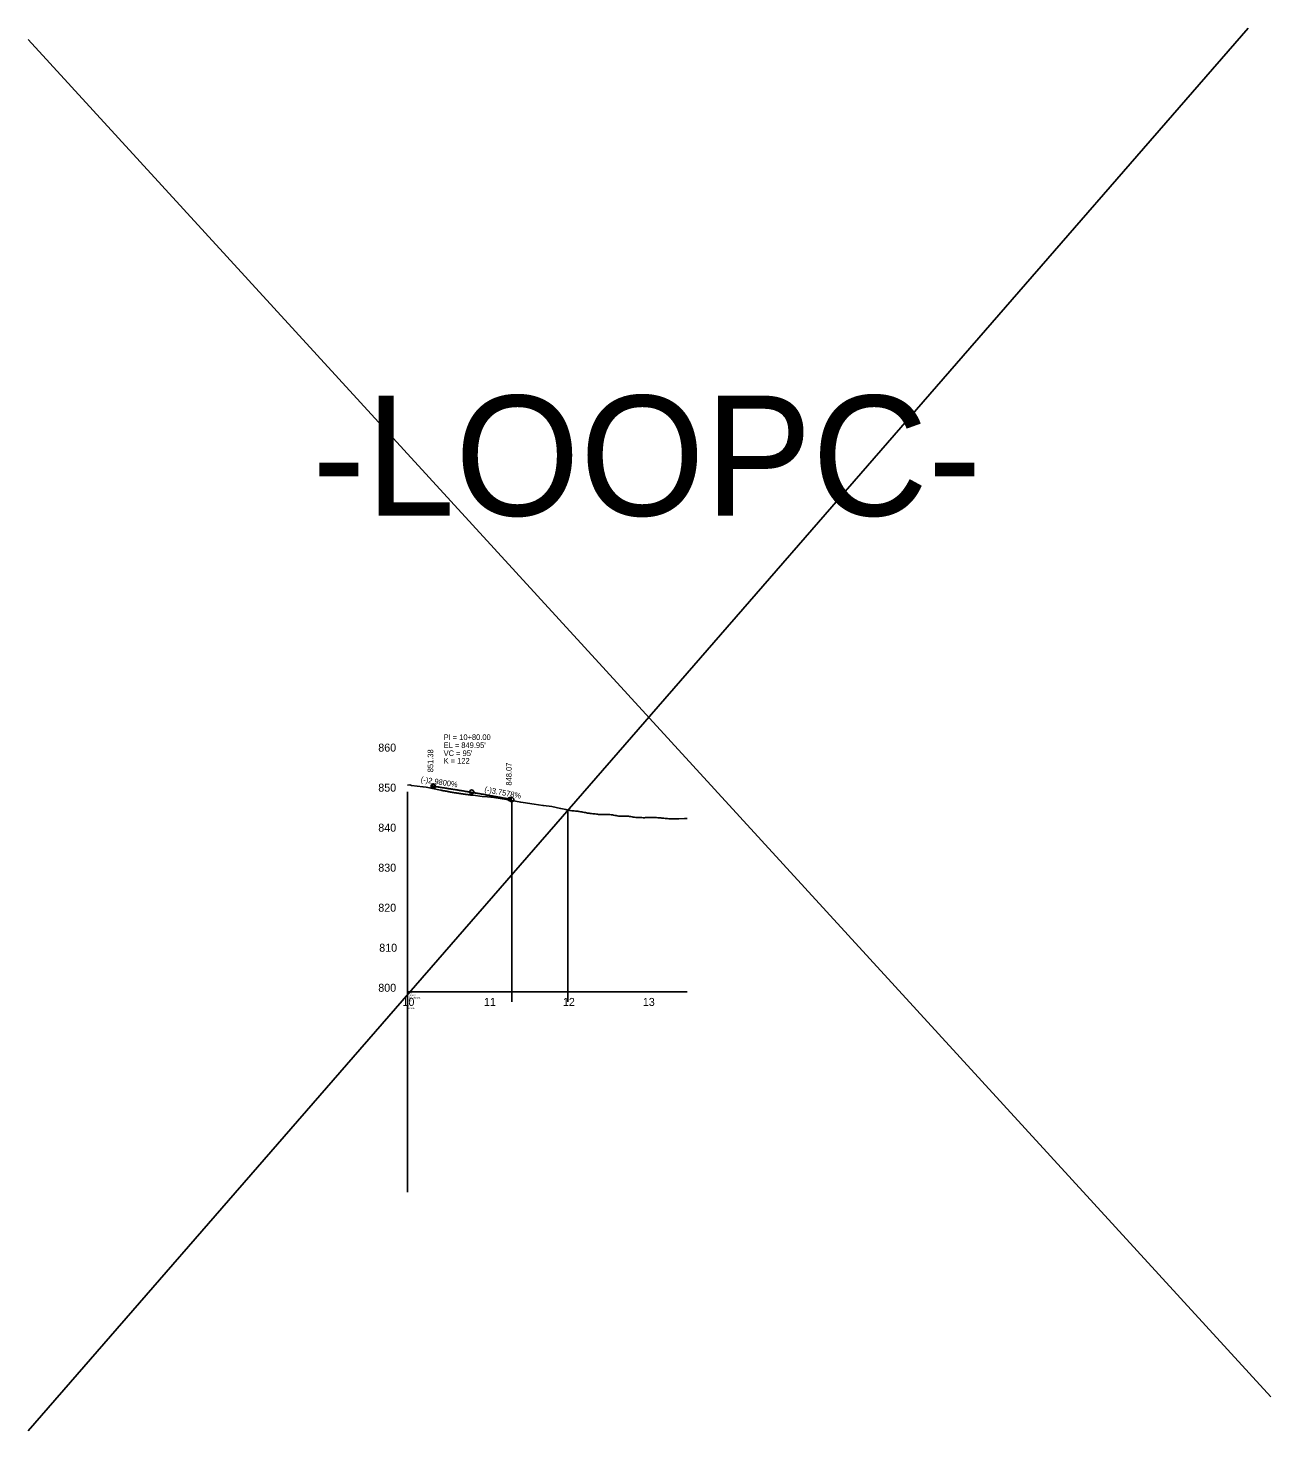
# Model space of a CAD drawing. Extents: x 570622 to 580296, y -55533 to -48575.
# Drawn here: x 578744 to 580296, y -52134 to -50382 of the extents above; entities that cross this region are included whole.
import ezdxf

# ---------------------------------------------------------------- set-up
doc = ezdxf.new("R2010")
doc.units = 0
for name, color, linetype in [('Default', 7, 'Continuous'), ('Exist Profile Cell', 7, 'Continuous'), ('Exist Vertical Profile Ground Line', 7, 'Continuous'), ('Exist Vertical Profile Horizontal Axis Label Major', 7, 'Continuous'), ('Exist Vertical Profile Vertical Axis Label', 7, 'Continuous'), ('Prop Vertical Profile Curve Label', 7, 'Continuous'), ('Prop Vertical Profile Grade', 7, 'Continuous'), ('Prop Vertical Profile Grade Label', 7, 'Continuous'), ('Prop VPI Label', 7, 'Continuous')]:
    doc.layers.add(name, color=color, linetype=linetype)

msp = doc.modelspace()

# ---------------------------------------------------------------- linework, layer by layer
at = {"layer": 'Default'}
for p, q in [((580267.7, -50381.9), (578744, -52134.4)), ((578744, -50396.2), (580296.2, -52091.7)), ((579348, -51598.5), (579348, -51346.9)), ((579418, -51598.5), (579418, -51359))]:
    msp.add_line(p, q, dxfattribs=at)
at = {"layer": 'Exist Profile Cell'}
for q in [(579218, -51336), (579567, -51586), (579218, -51836)]:
    msp.add_line((579218, -51586), q, dxfattribs=at)
at = {"layer": 'Exist Vertical Profile Ground Line'}
for points in [[(579218, -51327.6), (579220.8, -51327.5), (579220.8, -51327.5), (579223, -51328), (579237.2, -51329.6), (579241.2, -51330.4), (579259.3, -51334), (579260.1, -51334.1), (579260.8, -51334.3), (579261.6, -51334.4), (579262.4, -51334.6), (579263.1, -51334.7), (579263.9, -51334.8), (579264.7, -51335), (579265.5, -51335.1), (579266.2, -51335.3), (579267, -51335.4), (579267.8, -51335.6), (579268.5, -51335.7), (579269.3, -51335.9), (579270.1, -51336), (579270.9, -51336.1), (579271.6, -51336.3), (579272.4, -51336.4), (579273.2, -51336.5), (579273.2, -51336.6), (579273.9, -51336.7), (579274.7, -51336.8), (579275.5, -51337), (579275.6, -51337), (579276.3, -51337.1), (579277, -51337.2), (579277.8, -51337.3), (579278.6, -51337.4), (579279.3, -51337.5), (579280.1, -51337.7), (579280.4, -51337.7), (579280.9, -51337.8), (579281.7, -51337.9), (579282.4, -51338), (579283.2, -51338.1), (579284, -51338.2), (579284.7, -51338.4), (579285.5, -51338.5), (579286.3, -51338.6), (579287.1, -51338.7), (579287.8, -51338.8), (579288.6, -51338.9), (579289.4, -51339), (579290.1, -51339.1), (579290.9, -51339.2), (579291.7, -51339.3), (579292.5, -51339.4), (579293.2, -51339.5), (579294, -51339.6), (579294, -51339.6), (579294.8, -51339.7), (579295.5, -51339.8), (579296.3, -51339.9), (579297.1, -51340), (579297.9, -51340.1), (579300, -51340.3), (579311.2, -51341.7), (579317.6, -51342.4), (579325.8, -51343.3), (579341.5, -51345.8), (579346, -51346.5), (579359.3, -51349), (579362.4, -51349.4), (579376.1, -51351.4), (579386.9, -51353.2), (579387.6, -51353.3), (579398.3, -51354.5), (579408.9, -51356.7), (579409.2, -51356.7), (579415.5, -51358.1), (579417, -51358.5), (579418.6, -51358.8), (579420.1, -51359.2), (579420.4, -51359.2), (579420.7, -51359.3), (579421.6, -51359.4), (579423.2, -51359.6), (579424.7, -51359.7), (579426.2, -51359.9), (579427.8, -51360.1), (579429.3, -51360.2), (579430.8, -51360.4), (579431.8, -51360.5), (579432.2, -51360.6), (579432.4, -51360.6), (579433.9, -51360.9), (579435.4, -51361.2), (579437, -51361.5), (579438.5, -51361.8), (579440, -51362), (579441.6, -51362.3), (579442.7, -51362.5), (579443, -51362.6), (579443.1, -51362.6), (579444.6, -51362.8)], [(579444.6, -51362.8), (579446.2, -51363), (579447.7, -51363.2), (579449.2, -51363.4), (579450.8, -51363.5), (579452.3, -51363.7), (579453.8, -51363.9), (579455.4, -51364.1), (579455.6, -51364.1), (579455.8, -51364.2), (579456.9, -51364.2), (579458.4, -51364.2), (579459.9, -51364.2), (579461.5, -51364.2), (579463, -51364.2), (579464.5, -51364.2), (579466.1, -51364.2), (579467.6, -51364.2), (579469.1, -51364.2), (579470.2, -51364.2), (579470.3, -51364.2), (579470.7, -51364.3), (579472.2, -51364.6), (579473.7, -51364.9), (579475.3, -51365.2), (579476.8, -51365.5), (579477.3, -51365.6), (579478.3, -51365.8), (579479.9, -51366.1), (579481.3, -51366.4), (579481.4, -51366.4), (579481.5, -51366.4), (579482.9, -51366.4), (579484.5, -51366.4), (579485, -51366.4), (579486, -51366.4), (579487.5, -51366.5), (579489.1, -51366.5), (579490.6, -51366.5), (579492.1, -51366.5), (579493.4, -51366.5), (579493.5, -51366.5), (579493.7, -51366.5), (579495.2, -51366.8), (579496.7, -51367), (579498.3, -51367.3), (579499.8, -51367.5), (579500.2, -51367.6), (579501.3, -51367.8), (579502.9, -51368), (579504.3, -51368.3), (579504.4, -51368.3), (579504.5, -51368.3), (579505.9, -51368.3), (579507.5, -51368.3), (579509, -51368.3), (579510.5, -51368.3), (579512.1, -51368.4), (579513.6, -51368.4), (579513.7, -51368.4), (579513.7, -51368.4), (579515.1, -51368.3), (579516.4, -51368.3), (579516.7, -51368.3), (579517.6, -51368.3), (579518.2, -51368.2), (579519.7, -51368.2), (579521.3, -51368.1), (579522.8, -51368.1), (579524.1, -51368.1), (579524.2, -51368.1), (579524.3, -51368.1), (579525.9, -51368.2), (579527.4, -51368.3), (579528.9, -51368.3), (579530.5, -51368.4), (579532, -51368.5), (579533.5, -51368.6), (579534.8, -51368.7), (579534.8, -51368.7), (579535.1, -51368.8), (579535.9, -51368.8), (579536.6, -51368.9), (579538.1, -51369.1), (579539.7, -51369.2), (579541.2, -51369.4), (579542.7, -51369.5), (579544.3, -51369.7), (579545.8, -51369.9), (579546.1, -51369.9), (579546.1, -51369.9), (579555.8, -51369.7), (579556.8, -51369.7), (579564, -51369.4), (579567, -51369.3)]]:
    msp.add_lwpolyline(points, dxfattribs=at)
at = {"layer": 'Prop Vertical Profile Curve Label'}
for centre in [(579250.5, -51329.2), (579345.5, -51345.2)]:
    msp.add_circle(centre, 2.25, dxfattribs=at)
at = {"layer": 'Prop Vertical Profile Grade'}
for p, q in [((579250, -51329.1), (579250.5, -51329.2)), ((579345.5, -51345.2), (579348, -51345.7))]:
    msp.add_line(p, q, dxfattribs=at)
msp.add_spline([(579250.5, -51329.2), (579252.4, -51329.5), (579254.3, -51329.8), (579256.2, -51330), (579258.1, -51330.3), (579260, -51330.6), (579261.9, -51330.9), (579263.8, -51331.2), (579265.7, -51331.5), (579267.6, -51331.8), (579269.5, -51332.1), (579271.4, -51332.4), (579273.3, -51332.7), (579275.2, -51333), (579277.1, -51333.3), (579279, -51333.6), (579280.9, -51333.9), (579282.8, -51334.2), (579284.7, -51334.5), (579286.6, -51334.8), (579288.5, -51335.1), (579290.4, -51335.5), (579292.3, -51335.8), (579294.2, -51336.1), (579296.1, -51336.4), (579298, -51336.7), (579299.9, -51337), (579301.8, -51337.4), (579303.7, -51337.7), (579305.6, -51338), (579307.5, -51338.3), (579309.4, -51338.7), (579311.3, -51339), (579313.2, -51339.3), (579315.1, -51339.7), (579317, -51340), (579318.9, -51340.3), (579320.8, -51340.7), (579322.7, -51341), (579324.6, -51341.3), (579326.5, -51341.7), (579328.4, -51342), (579330.3, -51342.4), (579332.2, -51342.7), (579334.1, -51343.1), (579336, -51343.4), (579337.9, -51343.8), (579339.8, -51344.1), (579341.7, -51344.5), (579343.6, -51344.8), (579345.5, -51345.2)], degree=3, dxfattribs=at)
at = {"layer": 'Prop VPI Label'}
for p, q in [((579250.5, -51329.2), (579295.3, -51335.9)), ((579345.5, -51345.2), (579300.7, -51336.8))]:
    msp.add_line(p, q, dxfattribs=at)
for centre in [(579250, -51329.1), (579298, -51336.3), (579348, -51345.7)]:
    msp.add_circle(centre, 2.75, dxfattribs=at)

# ---------------------------------------------------------------- texts
at = {"layer": 'Default'}
msp.add_text('-LOOPC-', height=150, dxfattribs=at).set_placement((579098.8, -50991.1))
at = {"layer": 'Exist Profile Cell'}
for s, p in [('RDY', (579218, -51588)), ('LOOPC', (579218, -51591.3)), ('1000.000000', (579218, -51594.5)), ('800', (579218, -51597.8)), ('10', (579218, -51601)), ('2', (579218, -51604.3)), ('NOGAP', (579218, -51607.5))]:
    msp.add_text(s, height=2, dxfattribs=at).set_placement(p)
at = {"layer": 'Exist Vertical Profile Horizontal Axis Label Major'}
for s, p in [('10', (579211.6, -51603.5)), ('10', (579211.6, -51603.5)), ('11', (579313.4, -51603.5)), ('11', (579313.4, -51603.5)), ('12', (579412, -51603.5)), ('12', (579412, -51603.5)), ('13', (579511.8, -51603.5))]:
    msp.add_text(s, height=10, dxfattribs=at).set_placement(p)
at = {"layer": 'Exist Vertical Profile Vertical Axis Label'}
for s, p in [('860', (579181.4, -51285.8)), ('860', (579181.4, -51285.8)), ('850', (579181.4, -51335.8)), ('850', (579181.4, -51335.8)), ('840', (579181.4, -51385.8)), ('840', (579181.4, -51385.8)), ('830', (579181.4, -51435.8)), ('830', (579181.4, -51435.8)), ('820', (579181.4, -51485.8)), ('820', (579181.4, -51485.8)), ('810', (579182.6, -51535.8)), ('810', (579182.6, -51535.8)), ('800', (579181.4, -51585.8)), ('800', (579181.4, -51585.8))]:
    msp.add_text(s, height=10, dxfattribs=at).set_placement(p)
at = {"layer": 'Prop Vertical Profile Curve Label'}
for s, p in [("VC = 95'", (579263, -51291.3)), ('K = 122', (579263, -51300.8))]:
    msp.add_text(s, height=7, dxfattribs=at).set_placement(p)
at = {"layer": 'Prop Vertical Profile Grade Label'}
for s, rotation, p in [('(-)2.9800%', 351.5253, (579234.1, -51323.7)), ('(-)3.7578%', 349.3588, (579313.5, -51336.1))]:
    msp.add_text(s, height=7, rotation=rotation, dxfattribs=at).set_placement(p)
at = {"layer": 'Prop VPI Label'}
for s, p in [('PI = 10+80.00', (579263, -51271.3)), ("EL = 849.95'", (579263, -51281.3))]:
    msp.add_text(s, height=7, dxfattribs=at).set_placement(p)
for s, p in [('851.38', (579250, -51311.6)), ('848.07', (579348, -51328.2))]:
    msp.add_text(s, height=7, rotation=90, dxfattribs=at).set_placement(p)

doc.saveas('drawing.dxf')
